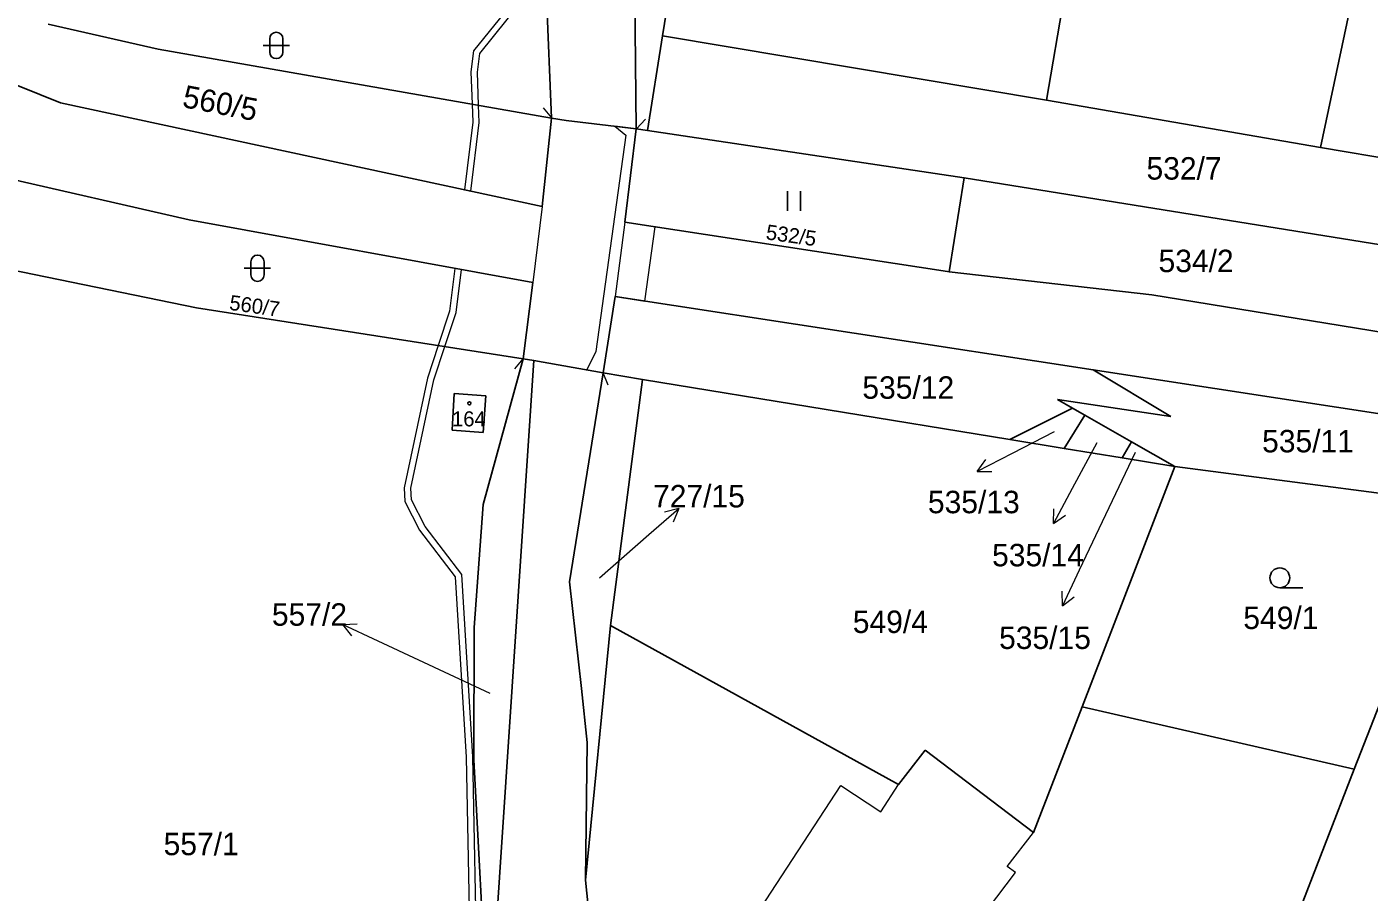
# Model space of a CAD drawing. Extents: x -701211 to -698780, y -1014269 to -1012378.
# Drawn here: x -700301.5 to -700199.9, y -1013298 to -1013232.4 of the extents above; entities that cross this region are included whole.
import ezdxf
from ezdxf.enums import TextEntityAlignment as Align

# ---------------------------------------------------------------- set-up
doc = ezdxf.new("R2010")
doc.units = 0
doc.header["$LTSCALE"] = 0.68
for name, color, linetype, lineweight in [('1', 7, 'Continuous', 25), ('13', 7, 'Continuous', 13), ('3', 7, 'Continuous', 25), ('4', 7, 'Continuous', 13), ('5', 7, 'Continuous', 25), ('7', 7, 'Continuous', 13)]:
    doc.layers.add(name, color=color, linetype=linetype, lineweight=lineweight)
doc.layers.add('2', color=7, linetype='Continuous')

msp = doc.modelspace()

# ---------------------------------------------------------------- linework, layer by layer
at = {"layer": '1'}
for p, q in [((-700203.56, -1013241.55), (-700195.73, -1013204.59)), ((-700253.38, -1013233.09), (-700249.13, -1013206.47)), ((-700224.3, -1013237.98), (-700219.83, -1013211.56)), ((-700262.25, -1013228.52), (-700261.8, -1013239.32)), ((-700255.37, -1013240.13), (-700255.51, -1013228.77)), ((-700312.97, -1013232.56), (-700298.98, -1013238.16)), ((-700299.91, -1013232.2), (-700291.57, -1013234.1)), ((-700254.52, -1013240.26), (-700253.38, -1013233.09)), ((-700253.38, -1013233.09), (-700224.3, -1013237.98)), ((-700291.57, -1013234.1), (-700261.8, -1013239.32)), ((-700298.98, -1013238.16), (-700262.49, -1013246.02)), ((-700224.3, -1013237.98), (-700203.56, -1013241.55)), ((-700262.49, -1013246.02), (-700261.8, -1013239.32)), ((-700261.8, -1013239.32), (-700260.69, -1013239.52)), ((-700260.69, -1013239.52), (-700255.37, -1013240.13)), ((-700256.23, -1013247.2), (-700255.37, -1013240.13)), ((-700255.37, -1013240.13), (-700254.52, -1013240.26)), ((-700254.52, -1013240.26), (-700230.54, -1013243.86)), ((-700203.56, -1013241.55), (-700182.87, -1013245.09)), ((-700303.94, -1013243.67), (-700289.22, -1013247.02)), ((-700230.54, -1013243.86), (-700231.69, -1013250.96)), ((-700188.84, -1013250.56), (-700230.54, -1013243.86)), ((-700289.22, -1013247.02), (-700263.21, -1013251.79)), ((-700231.81, -1013250.95), (-700256.23, -1013247.2)), ((-700288.68, -1013253.7), (-700308.46, -1013249.64)), ((-700231.69, -1013250.96), (-700231.81, -1013250.95)), ((-700216.33, -1013252.72), (-700231.69, -1013250.96)), ((-700263.21, -1013251.79), (-700263.93, -1013257.55)), ((-700256.96, -1013252.85), (-700257.87, -1013258.63)), ((-700220.78, -1013258.4), (-700256.96, -1013252.85)), ((-700190.18, -1013256.99), (-700216.33, -1013252.72)), ((-700263.93, -1013257.55), (-700288.68, -1013253.7)), ((-700263.93, -1013257.55), (-700266.97, -1013268.59)), ((-700263.12, -1013257.68), (-700263.93, -1013257.55)), ((-700263.12, -1013257.68), (-700266.45, -1013307.81)), ((-700263.12, -1013257.68), (-700257.87, -1013258.63)), ((-700191.02, -1013262.97), (-700220.78, -1013258.4)), ((-700214.89, -1013261.92), (-700220.78, -1013258.4)), ((-700260.44, -1013274.46), (-700257.87, -1013258.63)), ((-700257.87, -1013258.63), (-700254.9, -1013259.12)), ((-700257.33, -1013277.75), (-700254.9, -1013259.12)), ((-700254.9, -1013259.12), (-700227.09, -1013263.67)), ((-700269.31, -1013262.97), (-700269.16, -1013260.19)), ((-700269.16, -1013260.19), (-700266.76, -1013260.37)), ((-700266.76, -1013260.37), (-700266.97, -1013263.15)), ((-700227.09, -1013263.67), (-700222.35, -1013261.29)), ((-700223.49, -1013260.64), (-700222.35, -1013261.29)), ((-700223.49, -1013260.64), (-700214.89, -1013261.92)), ((-700222.35, -1013261.29), (-700221.4, -1013261.83)), ((-700221.4, -1013261.83), (-700222.98, -1013264.34)), ((-700221.4, -1013261.83), (-700217.88, -1013263.85)), ((-700269.31, -1013262.97), (-700266.97, -1013263.15)), ((-700227.09, -1013263.67), (-700222.98, -1013264.34)), ((-700222.98, -1013264.34), (-700218.59, -1013265.06)), ((-700217.88, -1013263.85), (-700218.59, -1013265.06)), ((-700217.88, -1013263.85), (-700214.6, -1013265.72)), ((-700218.59, -1013265.06), (-700214.6, -1013265.72)), ((-700214.6, -1013265.72), (-700221.62, -1013283.92)), ((-700193.17, -1013268.5), (-700214.6, -1013265.72)), ((-700266.97, -1013268.59), (-700267.65, -1013277.91)), ((-700193.17, -1013268.5), (-700201.01, -1013288.64)), ((-700259.53, -1013282.52), (-700260.44, -1013274.46)), ((-700267.65, -1013277.91), (-700267.68, -1013287.93)), ((-700259.22, -1013297.04), (-700257.33, -1013277.75)), ((-700257.33, -1013277.75), (-700235.51, -1013289.81)), ((-700259.09, -1013286.63), (-700259.53, -1013282.52)), ((-700221.62, -1013283.92), (-700225.29, -1013293.43)), ((-700221.62, -1013283.92), (-700201.01, -1013288.64)), ((-700259.22, -1013297.04), (-700259.09, -1013286.63)), ((-700267.68, -1013287.93), (-700266.77, -1013304.89)), ((-700235.51, -1013289.81), (-700233.49, -1013287.19)), ((-700233.49, -1013287.19), (-700225.29, -1013293.43)), ((-700201.01, -1013288.64), (-700213.69, -1013321.25)), ((-700258.19, -1013307.05), (-700259.22, -1013297.04))]:
    msp.add_line(p, q, dxfattribs=at)
at = {"layer": '13'}
for points in [[(-700264.57, -1013230.35), (-700267.71, -1013234.24), (-700267.9, -1013235.82), (-700267.81, -1013238.27), (-700267.76, -1013239.63), (-700268.39, -1013244.75), (-700267.9, -1013244.86), (-700267.26, -1013239.65), (-700267.31, -1013238.35), (-700267.4, -1013235.84), (-700267.23, -1013234.44), (-700264.11, -1013230.57), (-700261.8, -1013218.69), (-700262.3, -1013218.58)], [(-700257.87, -1013258.63), (-700256.96, -1013252.85), (-700254.72, -1013253.19), (-700253.94, -1013247.55), (-700256.23, -1013247.2), (-700255.37, -1013240.13), (-700256.99, -1013239.94), (-700256.16, -1013240.63), (-700258.44, -1013257.01), (-700259.13, -1013258.4)], [(-700270.37, -1013256.55), (-700271.18, -1013259.02), (-700272.94, -1013267.32), (-700272.9, -1013268.37), (-700271.78, -1013270.53), (-700269.08, -1013274.07), (-700268.26, -1013287.73), (-700267.92, -1013304.37), (-700266.23, -1013319.39), (-700266.33, -1013313.97), (-700267.42, -1013304.33), (-700267.76, -1013287.71), (-700268.58, -1013273.89), (-700271.36, -1013270.27), (-700272.4, -1013268.23), (-700272.44, -1013267.36), (-700270.7, -1013259.16), (-700269.87, -1013256.63), (-700269.02, -1013254.06), (-700268.62, -1013250.8), (-700269.12, -1013250.71), (-700269.52, -1013253.96)]]:
    msp.add_lwpolyline(points, close=True, dxfattribs=at)
at = {"layer": '3'}
for p, q in [((-700283.631, -1013233.821), (-700281.629, -1013233.821)), ((-700283.131, -1013233.321), (-700283.131, -1013234.322)), ((-700282.129, -1013234.322), (-700282.129, -1013233.321)), ((-700243.931, -1013246.36), (-700243.931, -1013244.86)), ((-700242.93, -1013246.36), (-700242.93, -1013244.86)), ((-700284.561, -1013250.201), (-700284.561, -1013251.202)), ((-700283.559, -1013251.202), (-700283.559, -1013250.201)), ((-700285.061, -1013250.701), (-700283.059, -1013250.701)), ((-700206.643, -1013274.9), (-700204.893, -1013274.9))]:
    msp.add_line(p, q, dxfattribs=at)
msp.add_circle((-700206.6429, -1013274.1498), 0.75, dxfattribs=at)
for centre, start, end in [((-700282.63, -1013233.3209), 0, 180), ((-700282.63, -1013234.3209), 180, 359.98789), ((-700284.06, -1013250.2009), 0, 180), ((-700284.06, -1013251.2009), 180, 359.98789)]:
    msp.add_arc(centre, 0.5, start, end, dxfattribs=at)
at = {"layer": '4'}
for p, q in [((-700262.429, -1013238.542), (-700261.8, -1013239.319)), ((-700254.675, -1013239.411), (-700255.369, -1013240.13)), ((-700262.49, -1013246.02), (-700263.21, -1013251.79)), ((-700256.23, -1013247.2), (-700256.96, -1013252.85)), ((-700264.573, -1013258.316), (-700263.931, -1013257.55)), ((-700257.496, -1013259.558), (-700257.87, -1013258.631)), ((-700245.98, -1013299.19), (-700239.88, -1013289.87)), ((-700239.88, -1013289.87), (-700236.85, -1013291.86)), ((-700236.85, -1013291.86), (-700235.51, -1013289.81)), ((-700227.28, -1013296.01), (-700225.29, -1013293.43)), ((-700226.67, -1013296.47), (-700227.28, -1013296.01)), ((-700231.61, -1013303), (-700226.67, -1013296.47))]:
    msp.add_line(p, q, dxfattribs=at)
at = {"layer": '5'}
msp.add_circle((-700268.0146, -1013260.9294), 0.1172, dxfattribs=at)
at = {"layer": '7'}
for p, q in [((-700229.574, -1013266.092), (-700228.454, -1013266.084)), ((-700252.155, -1013268.891), (-700253.239, -1013269.17)), ((-700223.779, -1013270.04), (-700222.867, -1013269.391)), ((-700223.098, -1013276.28), (-700222.221, -1013275.584)), ((-700277.63, -1013277.672), (-700276.934, -1013278.549))]:
    msp.add_line(p, q, dxfattribs=at)
for points in [[(-700223.73, -1013263.09), (-700226.9, -1013264.73), (-700229.574, -1013266.092), (-700228.909, -1013265.192)], [(-700220.51, -1013263.91), (-700222.37, -1013267.39), (-700223.779, -1013270.04), (-700223.751, -1013268.92)], [(-700217.59, -1013264.66), (-700221.83, -1013273.56), (-700223.098, -1013276.28), (-700223.129, -1013275.161)], [(-700258.17, -1013274.14), (-700254.42, -1013270.86), (-700252.155, -1013268.891), (-700252.582, -1013269.926)], [(-700266.44, -1013282.92), (-700274.91, -1013278.94), (-700277.63, -1013277.672), (-700276.511, -1013277.641)]]:
    msp.add_lwpolyline(points, dxfattribs=at)

# ---------------------------------------------------------------- texts
at = {"layer": '2'}
msp.add_text('560/5', height=1.7, rotation=349, dxfattribs=at).set_placement((-700289.821, -1013238.477))
for s, p in [('532/7', (-700216.74, -1013243.985)), ('534/2', (-700215.83, -1013250.995)), ('549/4', (-700238.98, -1013278.325)), ('549/1', (-700209.41, -1013278.025))]:
    msp.add_text(s, height=1.7, dxfattribs=at).set_placement(p)
for s, p in [('532/5', (-700243.7193, -1013248.7674)), ('560/7', (-700284.3493, -1013254.1074))]:
    msp.add_text(s, height=1.14, rotation=352, dxfattribs=at).set_placement(p, align=Align.CENTER)
for s, height, p in [('535/12', 1.7, (-700234.78, -1013260.585)), ('164', 1.14, (-700268.05, -1013262.675)), ('535/11', 1.7, (-700204.51, -1013264.645)), ('727/15', 1.7, (-700250.63, -1013268.815)), ('557/2', 1.7, (-700280.12, -1013277.775)), ('557/1', 1.7, (-700288.32, -1013295.155))]:
    msp.add_text(s, height=height, dxfattribs=at).set_placement(p, align=Align.CENTER)
for s, p in [('535/13', (-700226.339, -1013269.255)), ('535/14', (-700221.479, -1013273.275)), ('535/15', (-700220.949, -1013279.535))]:
    msp.add_text(s, height=1.7, dxfattribs=at).set_placement(p, align=Align.RIGHT)

doc.saveas('drawing.dxf')
